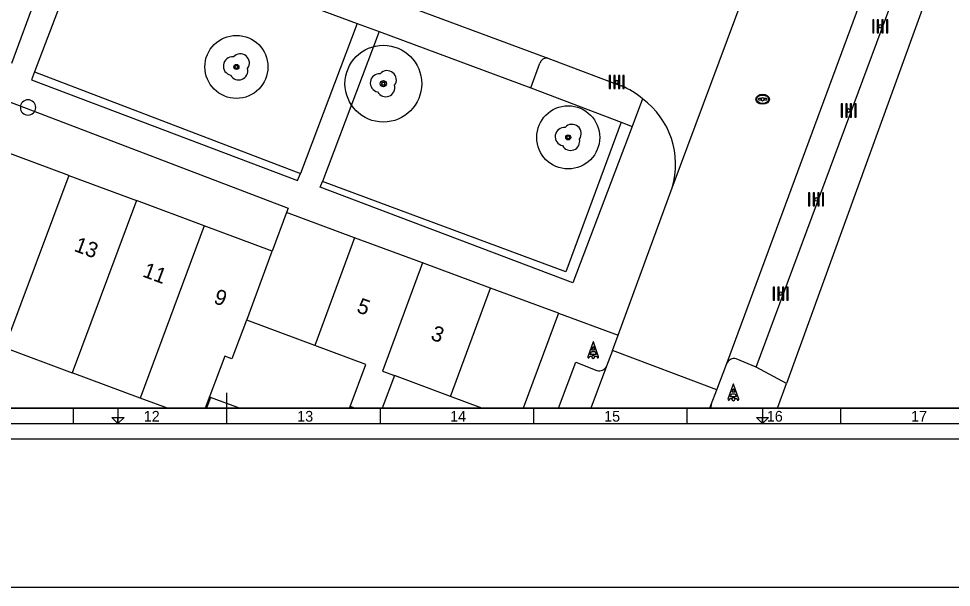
# Model space of a CAD drawing. Extents: x 192664 to 192925, y 446334 to 446521.
# Drawn here: x 192777.1 to 192837.8, y 446333.9 to 446370.9 of the extents above; entities that cross this region are included whole.
import ezdxf

# ---------------------------------------------------------------- set-up
doc = ezdxf.new("R2010")
doc.units = 0
for name, color, linetype in [('( Toegevoegd 29-11-2021 14_41_42) ondersteunend wegdeel vlak', 7, 'Continuous'), ('( Toegevoegd 29-11-2021 14_41_42) wegdeel vlak', 7, 'Continuous'), ('1010 viewport', 7, 'Continuous'), ('B-GV-GR-BOOM-S', 7, 'Continuous'), ('boom', 7, 'Continuous'), ('bovenleidingmast', 7, 'Continuous'), ('huisnummerreeks BGT', 7, 'Continuous'), ('inspectie-   rioolput', 7, 'Continuous'), ('kant open verharding', 7, 'Continuous'), ('kant verharding', 7, 'Continuous'), ('kast', 7, 'Continuous'), ('kolk', 7, 'Continuous'), ('pand op maaiveld vlak', 7, 'Continuous'), ('verkeerseiland - berm', 7, 'Continuous'), ('X-XX-AL-TEKENBLAD-S', 7, 'Continuous'), ('X-XX-AL-TEKENBLAD_KADER-G', 7, 'Continuous')]:
    doc.layers.add(name, color=color, linetype=linetype)

msp = doc.modelspace()

# ---------------------------------------------------------------- linework, layer by layer
at = {"layer": '( Toegevoegd 29-11-2021 14_41_42) ondersteunend wegdeel vlak'}
for p, q in [((192810.44, 446366.419), (192811.04, 446368.034)), ((192811.557, 446368.364), (192816.34, 446366.568)), ((192810.44, 446366.419), (192816.333, 446364.188)), ((192817.728, 446365.707), (192817.05, 446363.917)), ((192816.333, 446364.188), (192817.05, 446363.917))]:
    msp.add_line(p, q, dxfattribs=at)
for centre, radius, start, end in [((192811.476, 446367.92), 0.451, 79.68713, 165.41288), ((192814.314, 446361.753), 5.224, 49.19333, 67.18261)]:
    msp.add_arc(centre, radius, start, end, dxfattribs=at)
at = {"layer": '( Toegevoegd 29-11-2021 14_41_42) wegdeel vlak'}
for p, q in [((192816.13, 446350.319), (192819.665, 446359.922)), ((192812.252, 446351.747), (192816.13, 446350.319)), ((192815.762, 446349.319), (192816.13, 446350.319)), ((192815.762, 446349.319), (192815.385, 446348.295)), ((192822.569, 446346.767), (192815.762, 446349.319)), ((192827.102, 446347.165), (192825.128, 446348.244)), ((192822.207, 446345.813), (192822.569, 446346.767)), ((192826.522, 446345.556), (192827.102, 446347.165))]:
    msp.add_line(p, q, dxfattribs=at)
for points in [[(192758.17, 446371.875), (192758.285, 446372.185), (192775.949, 446365.705), (192777.106, 446365.279), (192794.631, 446358.595), (192794.529, 446358.306)], [(192778.115, 446367.463), (192777.917, 446366.939), (192795.253, 446360.386), (192795.43, 446360.855)], [(192817.05, 446363.917), (192813.194, 446353.729), (192796.724, 446359.963), (192796.861, 446360.326)]]:
    msp.add_lwpolyline(points, dxfattribs=at)
at = {"layer": '1010 viewport'}
msp.add_lwpolyline([(192675.743, 446509.756), (192860.643, 446509.756), (192860.643, 446345.556), (192675.743, 446345.556)], close=True, dxfattribs=at)
at = {"layer": 'B-GV-GR-BOOM-S'}
for centre, radius in [((192791.261, 446367.791), 2.054), ((192800.837, 446366.698), 2.5), ((192791.261, 446367.791), 0.164), ((192800.837, 446366.698), 0.2), ((192812.883, 446363.201), 2.054), ((192812.883, 446363.201), 0.164)]:
    msp.add_circle(centre, radius, dxfattribs=at)
at = {"layer": 'boom'}
for centre in [(192791.261, 446367.791), (192800.837, 446366.698), (192812.883, 446363.201)]:
    msp.add_circle(centre, 0.1, dxfattribs=at)
for centre, radius, start, end in [((192791.511, 446368.041), 0.6, 323.54458, 138.4658), ((192791.011, 446367.841), 0.6, 85.13702, 257.75442), ((192791.411, 446367.541), 0.6, 208.50578, 13.83556), ((192791.261, 446367.791), 0.1, 0, 180), ((192791.261, 446367.791), 0.1, 180, 0), ((192800.587, 446366.748), 0.6, 85.13702, 257.75442), ((192801.087, 446366.948), 0.6, 323.54458, 138.4658), ((192800.837, 446366.698), 0.1, 0, 180), ((192800.837, 446366.698), 0.1, 180, 0), ((192800.987, 446366.448), 0.6, 208.50578, 13.83556), ((192812.633, 446363.251), 0.6, 85.13702, 257.75442), ((192813.133, 446363.451), 0.6, 323.54458, 138.4658), ((192813.033, 446362.951), 0.6, 208.50578, 13.83556), ((192812.883, 446363.201), 0.1, 0, 180), ((192812.883, 446363.201), 0.1, 180, 0)]:
    msp.add_arc(centre, radius, start, end, dxfattribs=at)
at = {"layer": 'bovenleidingmast'}
for p, q in [((192814.503, 446349.875), (192814.162, 446348.902)), ((192814.862, 446348.902), (192814.521, 446349.875)), ((192823.634, 446347.124), (192823.293, 446346.151)), ((192823.993, 446346.151), (192823.652, 446347.124))]:
    msp.add_line(p, q, dxfattribs=at)
for points in [[(192814.634, 446349.252), (192814.704, 446349.052), (192814.32, 446349.052), (192814.39, 446349.252)], [(192823.765, 446346.501), (192823.835, 446346.301), (192823.451, 446346.301), (192823.521, 446346.501)]]:
    msp.add_lwpolyline(points, close=True, dxfattribs=at)
for points in [[(192814.521, 446349.572), (192814.599, 446349.352), (192814.425, 446349.352), (192814.503, 446349.572)], [(192814.256, 446348.869), (192814.285, 446348.952), (192814.425, 446348.952)], [(192814.599, 446348.952), (192814.739, 446348.952), (192814.768, 446348.869)], [(192823.652, 446346.821), (192823.73, 446346.601), (192823.556, 446346.601), (192823.634, 446346.821)], [(192823.387, 446346.118), (192823.416, 446346.201), (192823.556, 446346.201)], [(192823.73, 446346.201), (192823.87, 446346.201), (192823.899, 446346.118)]]:
    msp.add_lwpolyline(points, dxfattribs=at)
for centre, radius, start, end in [((192814.512, 446349.872), 0.01, 19.29005, 160.70995), ((192814.512, 446349.569), 0.01, 19.29005, 160.70995), ((192814.209, 446348.885), 0.05, 160.70995, 340.70995), ((192814.512, 446348.902), 0.1, 0, 180), ((192814.512, 446348.902), 0.1, 180, 0), ((192814.512, 446348.902), 0.1, 30, 150), ((192814.815, 446348.885), 0.05, 199.29005, 19.29005), ((192823.643, 446347.121), 0.01, 19.29005, 160.70995), ((192823.643, 446346.818), 0.01, 19.29005, 160.70995), ((192823.34, 446346.134), 0.05, 160.70995, 340.70995), ((192823.643, 446346.151), 0.1, 0, 180), ((192823.643, 446346.151), 0.1, 180, 0), ((192823.643, 446346.151), 0.1, 30, 150), ((192823.946, 446346.134), 0.05, 199.29005, 19.29005)]:
    msp.add_arc(centre, radius, start, end, dxfattribs=at)
at = {"layer": 'inspectie-   rioolput'}
for p, q in [((192825.457, 446365.723), (192825.3, 446365.723)), ((192825.3, 446365.648), (192825.457, 446365.648)), ((192825.8, 446365.723), (192825.643, 446365.723)), ((192825.643, 446365.648), (192825.8, 446365.648))]:
    msp.add_line(p, q, dxfattribs=at)
for centre, radius, start, end in [((192825.3, 446365.685), 0.0375, 90, 270), ((192825.55, 446365.685), 0.1, 0, 180), ((192825.55, 446365.685), 0.1, 157.97569, 180), ((192825.55, 446365.685), 0.1, 180, 202.02431), ((192825.55, 446365.685), 0.1, 180, 0), ((192825.55, 446365.685), 0.1, 0, 22.02431), ((192825.55, 446365.685), 0.1, 337.97569, 0), ((192825.8, 446365.685), 0.0375, 270, 90)]:
    msp.add_arc(centre, radius, start, end, dxfattribs=at)
for major_axis, ratio in [((-0.442, 0), 0.73911), ((-0.392, 0), 0.689655)]:
    msp.add_ellipse((192825.55, 446365.685), major_axis=major_axis, ratio=ratio, dxfattribs=at)
at = {"layer": 'kant open verharding'}
for p, q in [((192838.566, 446378.775), (192827.102, 446347.165)), ((192819.665, 446359.922), (192825.062, 446374.407))]:
    msp.add_line(p, q, dxfattribs=at)
at = {"layer": 'kant verharding'}
for p, q in [((192751.186, 446390.775), (192811.557, 446368.364)), ((192823.215, 446348.469), (192832.554, 446373.716)), ((192799.123, 446370.623), (192800.557, 446370.09)), ((192825.128, 446348.244), (192823.83, 446348.771)), ((192815.385, 446348.295), (192814.358, 446345.556)), ((192822.11, 446345.556), (192822.207, 446345.813))]:
    msp.add_line(p, q, dxfattribs=at)
for points in [[(192825.128, 446348.244), (192834.188, 446372.616), (192832.836, 446373.098)], [(192812.242, 446345.556), (192813.378, 446348.56), (192814.757, 446348.025)], [(192822.569, 446346.767), (192823.214, 446348.465), (192823.215, 446348.469)]]:
    msp.add_lwpolyline(points, dxfattribs=at)
for centre, radius, start, end in [((192814.573, 446361.434), 5.311, 343.46218, 53.56215), ((192823.683, 446348.293), 0.5, 72.9282, 159.37913), ((192814.917, 446348.518), 0.519, 252.04151, 334.48774), ((192822.668, 446345.642), 0.492, 159.69373, 190.16381)]:
    msp.add_arc(centre, radius, start, end, dxfattribs=at)
at = {"layer": 'kast'}
for start, end in [(0, 180), (180, 0)]:
    msp.add_arc((192777.682, 446365.148), 0.5, start, end, dxfattribs=at)
at = {"layer": 'kolk'}
for points in [[(192832.807, 446370.428), (192832.807, 446370.853), (192832.722, 446370.853), (192832.722, 446370.428), (192832.722, 446370.003), (192832.807, 446370.003)], [(192833.105, 446370.428), (192833.105, 446370.853), (192833.02, 446370.853), (192833.02, 446370.428), (192833.02, 446370.003), (192833.105, 446370.003)], [(192833.402, 446370.428), (192833.402, 446370.853), (192833.317, 446370.853), (192833.317, 446370.428), (192833.317, 446370.003), (192833.402, 446370.003)], [(192833.7, 446370.428), (192833.7, 446370.853), (192833.615, 446370.853), (192833.615, 446370.428), (192833.615, 446370.003), (192833.7, 446370.003)], [(192815.642, 446366.809), (192815.642, 446367.234), (192815.557, 446367.234), (192815.557, 446366.809), (192815.557, 446366.384), (192815.642, 446366.384)], [(192815.94, 446366.809), (192815.94, 446367.234), (192815.855, 446367.234), (192815.855, 446366.809), (192815.855, 446366.384), (192815.94, 446366.384)], [(192816.237, 446366.809), (192816.237, 446367.234), (192816.152, 446367.234), (192816.152, 446366.809), (192816.152, 446366.384), (192816.237, 446366.384)], [(192816.535, 446366.809), (192816.535, 446367.234), (192816.45, 446367.234), (192816.45, 446366.809), (192816.45, 446366.384), (192816.535, 446366.384)], [(192830.752, 446364.95), (192830.752, 446365.375), (192830.667, 446365.375), (192830.667, 446364.95), (192830.667, 446364.525), (192830.752, 446364.525)], [(192831.05, 446364.95), (192831.05, 446365.375), (192830.965, 446365.375), (192830.965, 446364.95), (192830.965, 446364.525), (192831.05, 446364.525)], [(192831.347, 446364.95), (192831.347, 446365.375), (192831.262, 446365.375), (192831.262, 446364.95), (192831.262, 446364.525), (192831.347, 446364.525)], [(192831.645, 446364.95), (192831.645, 446365.375), (192831.56, 446365.375), (192831.56, 446364.95), (192831.56, 446364.525), (192831.645, 446364.525)], [(192828.634, 446359.166), (192828.634, 446359.591), (192828.549, 446359.591), (192828.549, 446359.166), (192828.549, 446358.741), (192828.634, 446358.741)], [(192828.932, 446359.166), (192828.932, 446359.591), (192828.847, 446359.591), (192828.847, 446359.166), (192828.847, 446358.741), (192828.932, 446358.741)], [(192829.229, 446359.166), (192829.229, 446359.591), (192829.144, 446359.591), (192829.144, 446359.166), (192829.144, 446358.741), (192829.229, 446358.741)], [(192829.527, 446359.166), (192829.527, 446359.591), (192829.442, 446359.591), (192829.442, 446359.166), (192829.442, 446358.741), (192829.527, 446358.741)], [(192826.33, 446353.018), (192826.33, 446353.443), (192826.245, 446353.443), (192826.245, 446353.018), (192826.245, 446352.593), (192826.33, 446352.593)], [(192826.628, 446353.018), (192826.628, 446353.443), (192826.543, 446353.443), (192826.543, 446353.018), (192826.543, 446352.593), (192826.628, 446352.593)], [(192826.925, 446353.018), (192826.925, 446353.443), (192826.84, 446353.443), (192826.84, 446353.018), (192826.84, 446352.593), (192826.925, 446352.593)], [(192827.223, 446353.018), (192827.223, 446353.443), (192827.138, 446353.443), (192827.138, 446353.018), (192827.138, 446352.593), (192827.223, 446352.593)]]:
    msp.add_lwpolyline(points, close=True, dxfattribs=at)
for centre, start, end in [((192833.211, 446370.428), 0, 180), ((192833.211, 446370.428), 180, 0), ((192816.046, 446366.809), 0, 180), ((192816.046, 446366.809), 180, 0), ((192831.156, 446364.95), 0, 180), ((192831.156, 446364.95), 180, 0), ((192829.038, 446359.166), 0, 180), ((192829.038, 446359.166), 180, 0), ((192826.734, 446353.018), 0, 180), ((192826.734, 446353.018), 180, 0)]:
    msp.add_arc(centre, 0.1, start, end, dxfattribs=at)
at = {"layer": 'pand op maaiveld vlak'}
for p, q in [((192780.333, 446360.728), (192776.152, 446349.513)), ((192780.333, 446360.728), (192784.751, 446359.082)), ((192784.751, 446359.082), (192780.57, 446347.867)), ((192789.168, 446357.435), (192784.751, 446359.082)), ((192794.529, 446358.306), (192793.585, 446355.788)), ((192798.96, 446356.666), (192794.529, 446358.306)), ((192789.168, 446357.435), (192784.987, 446346.22)), ((192793.585, 446355.788), (192789.168, 446357.435)), ((192798.96, 446356.666), (192796.362, 446349.647)), ((192803.39, 446355.026), (192798.96, 446356.666)), ((192791.933, 446351.298), (192793.585, 446355.788)), ((192807.821, 446353.387), (192803.39, 446355.026)), ((192805.207, 446346.322), (192807.821, 446353.387)), ((192812.252, 446351.747), (192807.821, 446353.387)), ((192812.252, 446351.747), (192809.944, 446345.556)), ((192796.362, 446349.647), (192791.933, 446351.298)), ((192776.152, 446349.513), (192780.57, 446347.867)), ((192784.987, 446346.22), (192780.57, 446347.867)), ((192801.557, 446347.683), (192800.764, 446345.556)), ((192805.207, 446346.322), (192801.557, 446347.683)), ((192786.768, 446345.556), (192784.987, 446346.22)), ((192807.262, 446345.556), (192805.207, 446346.322)), ((192798.628, 446345.556), (192798.671, 446345.67)), ((192798.978, 446345.556), (192798.671, 446345.67))]:
    msp.add_line(p, q, dxfattribs=at)
for points in [[(192780.333, 446360.728), (192775.916, 446362.375), (192771.735, 446351.16), (192776.152, 446349.513)], [(192803.39, 446355.026), (192800.779, 446347.971), (192801.557, 446347.683)], [(192791.933, 446351.298), (192791.912, 446351.306), (192790.971, 446348.781), (192790.502, 446348.956), (192789.234, 446345.556)], [(192798.671, 446345.67), (192799.691, 446348.406), (192796.362, 446349.647)], [(192791.464, 446345.556), (192789.574, 446346.25), (192789.305, 446345.556)]]:
    msp.add_lwpolyline(points, dxfattribs=at)
at = {"layer": 'verkeerseiland - berm'}
for p, q in [((192780.156, 446377.668), (192776.611, 446368.02)), ((192781.749, 446377.077), (192778.115, 446367.463)), ((192781.749, 446377.077), (192799.123, 446370.623)), ((192799.123, 446370.623), (192795.43, 446360.855)), ((192800.557, 446370.09), (192796.861, 446360.326)), ((192800.557, 446370.09), (192810.44, 446366.419)), ((192778.115, 446367.463), (192795.43, 446360.855))]:
    msp.add_line(p, q, dxfattribs=at)
msp.add_lwpolyline([(192816.333, 446364.188), (192812.737, 446354.452), (192796.861, 446360.326)], dxfattribs=at)
at = {"layer": 'X-XX-AL-TEKENBLAD-S'}
for p, q in [((192780.643, 446344.556), (192780.643, 446345.556)), ((192783.543, 446345.556), (192783.543, 446344.556)), ((192800.643, 446344.556), (192800.643, 446345.556)), ((192810.643, 446344.556), (192810.643, 446345.556)), ((192820.643, 446344.556), (192820.643, 446345.556)), ((192825.543, 446345.556), (192825.543, 446344.556)), ((192830.643, 446344.556), (192830.643, 446345.556)), ((192783.543, 446344.956), (192783.543, 446344.556)), ((192783.543, 446344.556), (192783.543, 446344.956)), ((192825.543, 446344.956), (192825.543, 446344.556)), ((192825.543, 446344.556), (192825.543, 446344.956)), ((192674.743, 446344.556), (192908.543, 446344.556)), ((192671.743, 446343.556), (192909.543, 446343.556))]:
    msp.add_line(p, q, dxfattribs=at)
msp.add_lwpolyline([(192675.743, 446345.556), (192907.543, 446345.556), (192907.543, 446509.756), (192675.743, 446509.756)], close=True, dxfattribs=at)
for points in [[(192790.643, 446344.556), (192790.643, 446346.556)], [(192783.543, 446344.556), (192783.143, 446344.956), (192783.543, 446344.956)], [(192783.543, 446344.956), (192783.943, 446344.956), (192783.543, 446344.556)], [(192825.543, 446344.556), (192825.143, 446344.956), (192825.543, 446344.956)], [(192825.543, 446344.956), (192825.943, 446344.956), (192825.543, 446344.556)]]:
    msp.add_lwpolyline(points, dxfattribs=at)
at = {"layer": 'X-XX-AL-TEKENBLAD_KADER-G'}
msp.add_lwpolyline([(192664.22, 446520.974), (192925.029, 446520.974), (192925.029, 446333.894), (192664.22, 446333.894)], close=True, dxfattribs=at)

# ---------------------------------------------------------------- texts
at = {"layer": 'huisnummerreeks BGT'}
for s, rotation, p in [('13', 339.6, (192780.622, 446355.818)), ('11', 339.6, (192785.088, 446354.153)), ('9', 339.6, (192789.712, 446352.43)), ('5', 339.7, (192799.037, 446351.839)), ('3', 339.7, (192803.861, 446350.054))]:
    msp.add_text(s, height=1, rotation=rotation, dxfattribs=at).set_placement(p)
at = {"layer": 'X-XX-AL-TEKENBLAD-S'}
for s, p in [('12', (192785.224, 446344.685)), ('13', (192795.223, 446344.685)), ('14', (192805.189, 446344.685)), ('15', (192815.224, 446344.685)), ('16', (192825.824, 446344.685)), ('17', (192835.224, 446344.685))]:
    msp.add_text(s, height=0.7, dxfattribs=at).set_placement(p)

doc.saveas('drawing.dxf')
